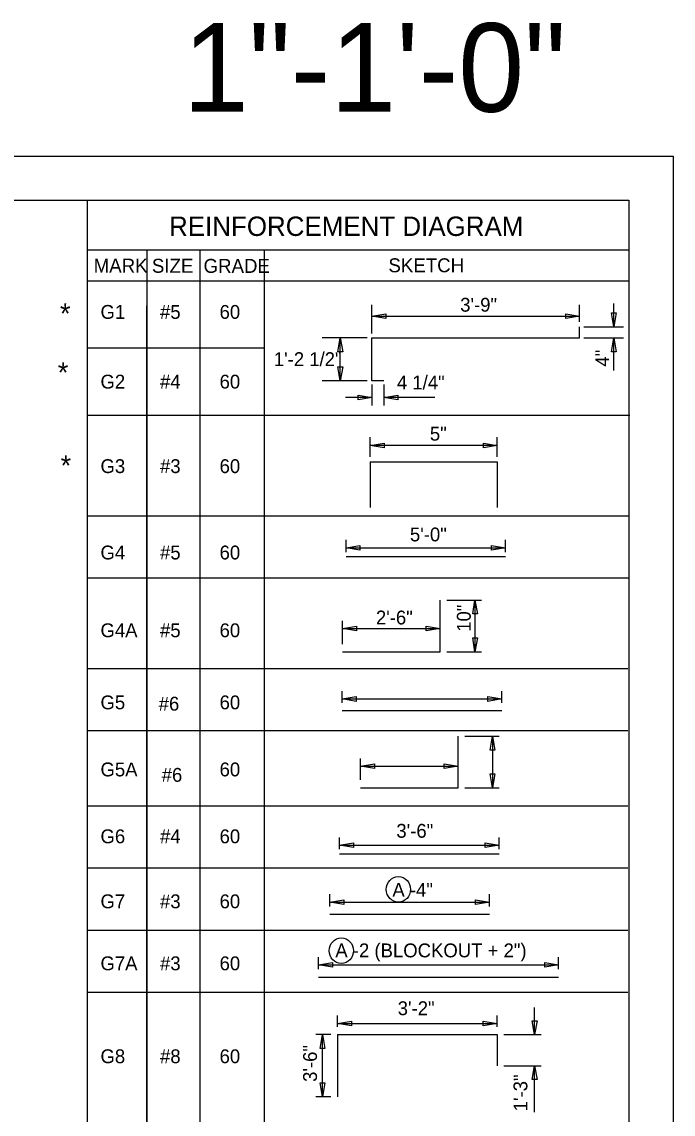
# Model space of a CAD drawing. Extents: x 0 to 34, y 0 to 23.5.
# Drawn here: x 26.65 to 34, y 11.18 to 23.51 of the extents above; entities that cross this region are included whole.
import ezdxf

# ---------------------------------------------------------------- set-up
doc = ezdxf.new("R2010")
doc.units = 0
for name, color, linetype in [('BORDER_ANNO_Cutsheet', 7, 'Continuous'), ('BRDG_ANNO_Anno-Sheet', 7, 'Continuous'), ('BRDG_ANNO_General-Notes', 7, 'Continuous'), ('BRDG_BASE_Obj-Line', 7, 'Continuous'), ('BRDG_BASE_Rebar', 7, 'Continuous'), ('Default', 7, 'Continuous')]:
    doc.layers.add(name, color=color, linetype=linetype)

# ---------------------------------------------------------------- blocks, each defined once
blk = doc.blocks.new('TERM')
at = {"layer": 'Default'}
for p, q in [((-1.6, -0.27), (-1.6, 0.27)), ((-1.6, 0.27), (0, 0)), ((0, 0), (-1.6, -0.27))]:
    blk.add_line(p, q, dxfattribs=at)

msp = doc.modelspace()

# ---------------------------------------------------------------- linework, layer by layer
at = {"layer": 'BORDER_ANNO_Cutsheet'}
msp.add_lwpolyline([(0, 22), (34, 22), (34, 0), (0, 0)], close=True, dxfattribs=at)
at = {"layer": 'BRDG_ANNO_Anno-Sheet'}
msp.add_lwpolyline([(1.5, 21.5), (33.5, 21.5), (33.5, 0.5), (1.5, 0.5)], close=True, dxfattribs=at)
at = {"layer": 'BRDG_ANNO_General-Notes'}
for p, q in [((30.601, 19.995), (30.601, 20.32)), ((32.945, 20.129), (32.945, 20.32)), ((33.303, 20.231), (33.356, 20.231)), ((33.329, 20.073), (33.303, 20.231)), ((33.329, 20.073), (33.329, 20.336)), ((33.356, 20.231), (33.329, 20.073)), ((30.601, 20.191), (30.759, 20.217)), ((30.601, 20.191), (32.945, 20.191)), ((30.759, 20.165), (30.601, 20.191)), ((30.759, 20.217), (30.759, 20.165)), ((32.788, 20.165), (32.788, 20.217)), ((32.788, 20.217), (32.945, 20.191)), ((32.945, 20.191), (32.788, 20.165)), ((32.992, 20.073), (33.439, 20.073)), ((30.547, 19.948), (30.04, 19.948)), ((30.218, 19.791), (30.244, 19.948)), ((30.244, 19.464), (30.244, 19.948)), ((30.244, 19.948), (30.271, 19.791)), ((32.992, 19.948), (33.439, 19.948)), ((33.303, 19.791), (33.329, 19.948)), ((33.329, 19.577), (33.329, 19.948)), ((33.329, 19.948), (33.356, 19.791)), ((30.271, 19.791), (30.218, 19.791)), ((33.356, 19.791), (33.303, 19.791)), ((30.218, 19.621), (30.271, 19.621)), ((30.244, 19.464), (30.218, 19.621)), ((30.271, 19.621), (30.244, 19.464)), ((30.547, 19.464), (30.04, 19.464)), ((30.601, 19.422), (30.601, 19.184)), ((30.734, 19.422), (30.734, 19.184)), ((30.601, 19.273), (30.302, 19.273)), ((30.444, 19.246), (30.444, 19.299)), ((30.444, 19.299), (30.601, 19.273)), ((30.601, 19.273), (30.444, 19.246)), ((30.734, 19.273), (30.892, 19.299)), ((31.311, 19.273), (30.734, 19.273)), ((30.892, 19.246), (30.734, 19.273)), ((30.892, 19.299), (30.892, 19.246)), ((30.583, 18.603), (30.583, 18.826)), ((32.016, 18.603), (32.016, 18.826)), ((32.016, 18.733), (30.583, 18.733)), ((30.309, 17.528), (30.309, 17.666)), ((32.11, 17.528), (32.11, 17.666)), ((30.309, 17.578), (30.466, 17.605)), ((30.309, 17.578), (32.11, 17.578)), ((30.466, 17.552), (30.309, 17.578)), ((30.466, 17.605), (30.466, 17.552)), ((31.952, 17.552), (31.952, 17.605)), ((31.952, 17.605), (32.11, 17.578)), ((32.11, 17.578), (31.952, 17.552)), ((31.445, 16.987), (31.839, 16.987)), ((31.738, 16.83), (31.764, 16.987)), ((31.764, 16.987), (31.764, 16.403)), ((31.764, 16.987), (31.791, 16.83)), ((31.791, 16.83), (31.738, 16.83)), ((30.27, 16.491), (30.27, 16.754)), ((30.27, 16.666), (30.427, 16.692)), ((30.27, 16.666), (31.37, 16.666)), ((30.427, 16.64), (30.27, 16.666)), ((30.427, 16.692), (30.427, 16.64)), ((31.213, 16.64), (31.213, 16.692)), ((31.213, 16.692), (31.37, 16.666)), ((31.37, 16.666), (31.213, 16.64)), ((31.738, 16.561), (31.791, 16.561)), ((31.764, 16.403), (31.738, 16.561)), ((31.791, 16.561), (31.764, 16.403)), ((31.445, 16.403), (31.839, 16.403)), ((30.267, 15.827), (30.267, 15.958)), ((32.068, 15.827), (32.068, 15.958)), ((30.267, 15.871), (30.424, 15.897)), ((30.267, 15.871), (32.068, 15.871)), ((30.424, 15.844), (30.267, 15.871)), ((30.424, 15.897), (30.424, 15.844)), ((31.91, 15.844), (31.91, 15.897)), ((31.91, 15.897), (32.068, 15.871)), ((32.068, 15.871), (31.91, 15.844)), ((31.648, 15.452), (32.037, 15.452)), ((31.936, 15.294), (31.962, 15.452)), ((31.962, 15.452), (31.962, 14.868)), ((31.962, 15.452), (31.988, 15.294)), ((31.988, 15.294), (31.936, 15.294)), ((30.473, 14.956), (30.473, 15.199)), ((31.573, 14.956), (31.573, 15.199)), ((30.473, 15.112), (30.63, 15.138)), ((30.473, 15.112), (31.573, 15.112)), ((30.63, 15.085), (30.473, 15.112)), ((30.63, 15.138), (30.63, 15.085)), ((31.416, 15.085), (31.416, 15.138)), ((31.416, 15.138), (31.573, 15.112)), ((31.573, 15.112), (31.416, 15.085)), ((31.936, 15.026), (31.988, 15.026)), ((31.962, 14.868), (31.936, 15.026)), ((31.988, 15.026), (31.962, 14.868)), ((31.648, 14.868), (32.037, 14.868)), ((30.234, 14.174), (30.234, 14.307)), ((32.035, 14.174), (32.035, 14.307)), ((30.234, 14.22), (30.392, 14.246)), ((30.234, 14.22), (32.035, 14.22)), ((30.392, 14.194), (30.234, 14.22)), ((30.392, 14.246), (30.392, 14.194)), ((31.877, 14.194), (31.877, 14.246)), ((31.877, 14.246), (32.035, 14.22)), ((32.035, 14.22), (31.877, 14.194)), ((30.126, 13.527), (30.126, 13.666)), ((30.126, 13.578), (30.283, 13.604)), ((30.126, 13.578), (31.927, 13.578)), ((30.283, 13.552), (30.126, 13.578)), ((30.283, 13.604), (30.283, 13.552)), ((31.769, 13.552), (31.769, 13.604)), ((31.769, 13.604), (31.927, 13.578)), ((31.927, 13.578), (31.769, 13.552)), ((31.927, 13.527), (31.927, 13.666)), ((30, 12.819), (30, 12.957)), ((32.708, 12.819), (32.708, 12.957)), ((30, 12.869), (30.157, 12.896)), ((30, 12.869), (32.708, 12.869)), ((30.157, 12.843), (30, 12.869)), ((30.157, 12.896), (30.157, 12.843)), ((32.551, 12.843), (32.551, 12.896)), ((32.551, 12.896), (32.708, 12.869)), ((32.708, 12.869), (32.551, 12.843)), ((32.437, 12.082), (32.437, 12.387)), ((30.212, 12.169), (30.212, 12.296)), ((30.212, 12.208), (30.37, 12.234)), ((30.212, 12.208), (32.013, 12.208)), ((30.37, 12.182), (30.212, 12.208)), ((30.37, 12.234), (30.37, 12.182)), ((31.856, 12.182), (31.856, 12.234)), ((31.856, 12.234), (32.013, 12.208)), ((32.013, 12.208), (31.856, 12.182)), ((32.013, 12.169), (32.013, 12.296)), ((32.411, 12.239), (32.464, 12.239)), ((32.437, 12.082), (32.411, 12.239)), ((32.464, 12.239), (32.437, 12.082)), ((30.137, 12.082), (29.967, 12.082)), ((30.016, 11.924), (30.042, 12.082)), ((30.042, 11.381), (30.042, 12.082)), ((30.042, 12.082), (30.069, 11.924)), ((32.088, 12.082), (32.512, 12.082)), ((30.069, 11.924), (30.016, 11.924)), ((32.088, 11.731), (32.512, 11.731)), ((32.411, 11.574), (32.437, 11.731)), ((32.437, 11.206), (32.437, 11.731)), ((32.437, 11.731), (32.464, 11.574)), ((30.016, 11.539), (30.069, 11.539)), ((30.042, 11.381), (30.016, 11.539)), ((30.069, 11.539), (30.042, 11.381)), ((32.464, 11.574), (32.411, 11.574)), ((30.137, 11.381), (29.967, 11.381))]:
    msp.add_line(p, q, dxfattribs=at)
for centre in [(30.9, 13.721), (30.256, 13.029)]:
    msp.add_ellipse(centre, major_axis=(0, 0.144), ratio=0.952381, dxfattribs=at)
at = {"layer": 'BRDG_BASE_Obj-Line'}
for p, q in [((27.387, 21.499), (27.387, 7.095)), ((27.387, 20.941), (33.506, 20.941)), ((28.06, 20.941), (28.06, 7.095)), ((28.66, 20.941), (28.66, 7.095)), ((29.386, 20.941), (29.386, 7.095)), ((27.387, 20.591), (33.5, 20.591)), ((28.059, 20.308), (28.059, 10.039)), ((27.387, 19.835), (29.386, 19.835)), ((27.387, 19.076), (33.512, 19.076)), ((27.387, 17.938), (33.494, 17.938)), ((27.387, 17.237), (33.506, 17.237)), ((27.387, 16.214), (33.488, 16.214)), ((27.387, 15.513), (33.488, 15.513)), ((27.387, 14.663), (33.488, 14.663)), ((27.387, 13.963), (33.488, 13.963)), ((27.387, 13.262), (33.488, 13.262)), ((27.387, 12.562), (33.488, 12.562))]:
    msp.add_line(p, q, dxfattribs=at)
at = {"layer": 'BRDG_BASE_Rebar'}
for p, q in [((30.583, 18.548), (32.016, 18.548)), ((30.583, 18.548), (30.583, 18.033)), ((32.016, 18.548), (32.016, 18.033)), ((30.309, 17.48), (32.11, 17.48)), ((31.37, 16.403), (31.37, 16.987)), ((30.27, 16.403), (31.37, 16.403)), ((30.267, 15.74), (32.068, 15.74)), ((31.573, 14.868), (31.573, 15.452)), ((30.473, 14.868), (31.573, 14.868)), ((30.234, 14.123), (32.035, 14.123)), ((30.126, 13.44), (31.927, 13.44)), ((30, 12.731), (32.708, 12.731)), ((30.212, 12.082), (32.013, 12.082)), ((30.212, 12.082), (30.212, 11.381)), ((32.013, 12.082), (32.013, 11.731))]:
    msp.add_line(p, q, dxfattribs=at)
msp.add_lwpolyline([(30.734, 19.464), (30.601, 19.464), (30.601, 19.948), (32.945, 19.948), (32.945, 20.073)], dxfattribs=at)

# ---------------------------------------------------------------- block references
at = {"layer": 'BRDG_ANNO_General-Notes', "xscale": 0.09765625, "yscale": 0.0976318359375, "rotation": 180}
msp.add_blockref('TERM', (30.583, 18.733), dxfattribs=at)
at = {"layer": 'BRDG_ANNO_General-Notes', "xscale": 0.09765625, "yscale": 0.0976318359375}
msp.add_blockref('TERM', (32.016, 18.733), dxfattribs=at)

# ---------------------------------------------------------------- texts
at = {"layer": 'BRDG_ANNO_Anno-Sheet'}
msp.add_text('1"-1\'-0"', height=1, dxfattribs=at).set_placement((28.467, 22.5))
at = {"layer": 'BRDG_ANNO_General-Notes'}
for s, height, p in [('REINFORCEMENT DIAGRAM', 0.21875, (28.312, 21.098)), ('MARK', 0.1576, (27.461, 20.684)), ('SIZE', 0.1576, (28.118, 20.682)), ('GRADE', 0.1575, (28.701, 20.681)), ('SKETCH', 0.1575, (30.787, 20.688)), ('3\'-9"', 0.1562, (31.597, 20.243)), ('*', 0.229, (27.081, 20.108)), ('G1', 0.1562, (27.538, 20.162)), ('#5', 0.1562, (28.21, 20.162)), ('60', 0.1562, (28.882, 20.162)), ('1\'-2 1/2"', 0.1562, (29.494, 19.629)), ('*', 0.229, (27.056, 19.442)), ('G2', 0.1562, (27.538, 19.375)), ('#4', 0.1562, (28.21, 19.375)), ('60', 0.1562, (28.882, 19.375)), ('4 1/4"', 0.1562, (30.883, 19.366)), ('5"', 0.1562, (31.255, 18.787)), ('*', 0.229, (27.088, 18.392)), ('G3', 0.1562, (27.538, 18.421)), ('#3', 0.1562, (28.21, 18.421)), ('60', 0.1562, (28.882, 18.421)), ('5\'-0"', 0.1562, (31.03, 17.65)), ('G4', 0.1562, (27.538, 17.446)), ('#5', 0.1562, (28.21, 17.446)), ('60', 0.1562, (28.882, 17.446)), ('2\'-6"', 0.1562, (30.646, 16.712)), ('G4A', 0.1562, (27.538, 16.568)), ('#5', 0.1562, (28.21, 16.568)), ('60', 0.1562, (28.882, 16.568)), ('G5', 0.1562, (27.538, 15.754)), ('60', 0.1562, (28.882, 15.754)), ('#6', 0.1562, (28.195, 15.739)), ('G5A', 0.1562, (27.538, 14.997)), ('#6', 0.1562, (28.229, 14.936)), ('60', 0.1562, (28.882, 14.997)), ('3\'-6"', 0.1562, (30.877, 14.304)), ('G6', 0.1562, (27.538, 14.242)), ('#4', 0.1562, (28.21, 14.242)), ('60', 0.1562, (28.882, 14.242)), ('A -4"', 0.1562, (30.832, 13.638)), ('G7', 0.1562, (27.538, 13.508)), ('#3', 0.1562, (28.21, 13.508)), ('60', 0.1562, (28.882, 13.508)), ('A -2 (BLOCKOUT + 2")', 0.15625, (30.188, 12.954)), ('G7A', 0.1562, (27.538, 12.808)), ('#3', 0.1562, (28.21, 12.808)), ('60', 0.1562, (28.882, 12.808)), ('3\'-2"', 0.1562, (30.892, 12.301)), ('G8', 0.1562, (27.538, 11.759)), ('#8', 0.1562, (28.21, 11.759)), ('60', 0.1562, (28.882, 11.759))]:
    msp.add_text(s, height=height, dxfattribs=at).set_placement(p)
for s, p in [('4"', (33.278, 19.623)), ('10"', (31.716, 16.629)), ('3\'-6"', (29.981, 11.548)), ('1\'-3"', (32.355, 11.216))]:
    msp.add_text(s, height=0.1562, rotation=90, dxfattribs=at).set_placement(p)

doc.saveas('drawing.dxf')
